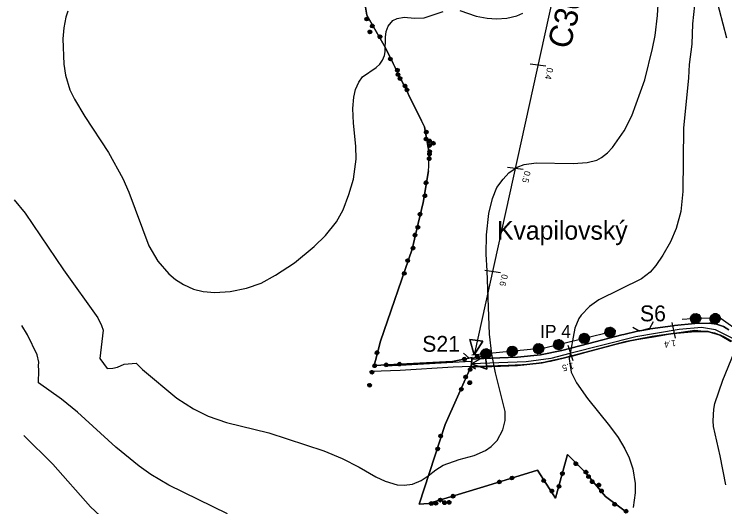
# Model space of a CAD drawing. Extents: x -645676 to -642474, y -1077513 to -1072613.
# Drawn here: x -644931 to -644259, y -1076247 to -1075781 of the extents above; entities that cross this region are included whole.
import ezdxf

# ---------------------------------------------------------------- set-up
doc = ezdxf.new("R2010")
doc.units = 0
for name, color, linetype in [('_cesty_Kunci', 7, 'Continuous'), ('Interak_n__prvek___l_niov____navr_en_', 7, 'Continuous'), ('katastr_ln___zem____popis', 7, 'Continuous'), ('KULTURY_STAV', 7, 'Continuous'), ('OBVOD_PU', 7, 'Continuous'), ('Odvodnen__cesty_pod_lnou_dren_____navr_en_', 7, 'Continuous'), ('PC_NAVRH', 7, 'Continuous'), ('PC_OBJ_POPIS_NAVRH', 7, 'Continuous'), ('PC_OBJ_POPIS_STAV', 7, 'Continuous'), ('PC_OBJEKTY_NAVRH', 7, 'Continuous'), ('PC_OBJEKTY_STAV', 7, 'Continuous'), ('PC_POPIS_NAVRH', 7, 'Continuous'), ('PC_STAN_NAVRH', 7, 'Continuous'), ('SPRAV_HR_STAV', 7, 'Continuous'), ('USES_IP_NAVRH', 7, 'Continuous'), ('VRSTEVNICE', 7, 'Continuous')]:
    doc.layers.add(name, color=color, linetype=linetype)

# ---------------------------------------------------------------- blocks, each defined once
blk = doc.blocks.new('$944')
blk.add_line((0, 1.5), (0, -1.5))
blk = doc.blocks.new('$920')
for points in [[(0, 0), (-2.8, 1.25), (-2.8, -1.25), (0, 0)], [(-2.8, 1.25), (0, 0), (-2.8, -1.25), (-2.8, 1.25)]]:
    blk.add_lwpolyline(points)
blk = doc.blocks.new('$934')
blk.add_lwpolyline([(-2, -1), (-1, 0), (1, 0), (2, -1)])
blk = doc.blocks.new('$935')
blk.add_lwpolyline([(-2, -1), (-1, 0), (1, 0), (2, -1)])
blk = doc.blocks.new('6$4100')
blk.add_lwpolyline([(0.19, 0.72), (0.53, 0.53), (0.72, 0.19), (0.72, -0.2), (0.53, -0.54), (0.19, -0.73), (-0.2, -0.73), (-0.54, -0.54), (-0.73, -0.2), (-0.75, 0.12), (-0.54, 0.52), (-0.2, 0.71), (0.19, 0.71), (0.2, 0.67), (-0.2, 0.67), (-0.36, 0.59), (0.36, 0.59), (0.44, 0.51), (-0.44, 0.51), (-0.52, 0.43), (0.52, 0.43), (0.6, 0.35), (-0.6, 0.35), (-0.6, 0.27), (0.6, 0.27), (0.68, 0.19), (-0.59, 0.19), (-0.68, 0.19), (-0.68, 0.11), (0.59, 0.11), (0.68, 0.11), (0.68, 0.03), (-0.59, 0.03), (-0.68, 0.03), (-0.68, -0.05), (0.59, -0.05), (0.68, -0.05), (0.68, -0.13), (-0.59, -0.13), (-0.68, -0.13), (-0.68, -0.21), (0.59, -0.21), (0.68, -0.21), (0.6, -0.29), (-0.6, -0.29), (-0.6, -0.37), (0.6, -0.37), (0.52, -0.45), (-0.52, -0.45), (-0.44, -0.53), (0.44, -0.53), (0.36, -0.61), (-0.36, -0.61), (-0.2, -0.69), (0.2, -0.69)])
blk = doc.blocks.new('2$0620')
for points in [[(-1.07, 0.32), (-0.88, 0.13), (-0.88, -0.14), (-1.07, -0.33), (-1.34, -0.33), (-1.53, -0.14), (-1.53, 0.13), (-1.34, 0.32), (-1.07, 0.32), (-1.08, 0.28), (-1.32, 0.28), (-1.4, 0.2), (-1, 0.2), (-0.92, 0.12), (-1.48, 0.12), (-1.48, 0.04), (-0.92, 0.04), (-0.92, -0.04), (-1.48, -0.04), (-1.48, -0.12), (-0.92, -0.12), (-1, -0.2), (-1.4, -0.2), (-1.32, -0.28), (-1.08, -0.28)], [(1.43, 0.32), (1.62, 0.13), (1.62, -0.14), (1.43, -0.33), (1.16, -0.33), (0.97, -0.14), (0.97, 0.13), (1.16, 0.32), (1.43, 0.32), (1.4, 0.28), (1.16, 0.28), (1.08, 0.2), (1.48, 0.2), (1.56, 0.12), (1, 0.12), (1, 0.04), (1.56, 0.04), (1.56, -0.04), (1, -0.04), (1, -0.12), (1.56, -0.12), (1.48, -0.2), (1.08, -0.2), (1.16, -0.28), (1.4, -0.28)]]:
    blk.add_lwpolyline(points)

msp = doc.modelspace()

# ---------------------------------------------------------------- linework, layer by layer
at = {"layer": '_cesty_Kunci'}
for points in [[(-644581.13, -1076113.83), (-644566.09, -1076113.29), (-644515.99, -1076110.21), (-644498.33, -1076109.46)], [(-644593.08, -1076118.86), (-644565.87, -1076117.78), (-644515.75, -1076114.7), (-644498.85, -1076113.98)]]:
    msp.add_lwpolyline(points, dxfattribs=at)
at = {"layer": 'KULTURY_STAV'}
for points in [[(-644255.1, -1076079.71), (-644260.19, -1076076.56), (-644266.6, -1076074.35), (-644271.34, -1076073.61), (-644272.85, -1076073.38), (-644273.34, -1076073.4), (-644287.12, -1076073.87), (-644306.47, -1076075.81), (-644308.04, -1076075.97), (-644329.62, -1076078.88), (-644330.08, -1076078.97), (-644339.27, -1076080.54), (-644339.74, -1076080.65), (-644341.46, -1076081.05), (-644354.26, -1076084.02), (-644356.27, -1076084.54), (-644387.65, -1076092.6), (-644413.15, -1076099.38), (-644433.25, -1076103.25), (-644454.88, -1076105.48), (-644463.83, -1076105.91), (-644479.69, -1076106.66), (-644493.74, -1076107.19), (-644498.09, -1076107.36), (-644497.92, -1076105.85), (-644516.5, -1076109.6), (-644590.53, -1076113.44), (-644589.33, -1076108.84), (-644584.52, -1076090.43), (-644554.64, -1076003.63), (-644548.81, -1075979.12), (-644544.12, -1075959.37), (-644539.08, -1075929.42), (-644538.91, -1075925.07), (-644538.45, -1075912.82), (-644542.92, -1075887.94), (-644545.74, -1075882.23), (-644570.68, -1075831.68), (-644572.46, -1075828.07), (-644579.81, -1075813.18), (-644597.61, -1075782.29), (-644598.84, -1075774.6)], [(-644253.28, -1076090.66), (-644263.37, -1076084.84), (-644271.64, -1076082.31), (-644274.66, -1076081.39), (-644286.82, -1076081.21), (-644307.62, -1076083.15), (-644327.55, -1076086.11), (-644353.37, -1076091.11), (-644385.16, -1076099.62), (-644411.62, -1076106.58), (-644423.38, -1076109.21), (-644431.6, -1076111.04), (-644446.18, -1076112.61), (-644454.96, -1076113.55), (-644479.38, -1076114.39), (-644494.42, -1076114.72), (-644495.74, -1076114.74), (-644499.22, -1076114.82), (-644498.85, -1076113.98), (-644497.92, -1076105.85), (-644498.09, -1076107.36), (-644493.74, -1076107.19), (-644479.69, -1076106.66), (-644463.83, -1076105.91), (-644454.88, -1076105.48), (-644433.25, -1076103.25), (-644413.15, -1076099.38), (-644387.65, -1076092.6), (-644356.27, -1076084.54), (-644354.26, -1076084.02), (-644341.46, -1076081.05), (-644339.74, -1076080.65), (-644339.27, -1076080.54), (-644330.08, -1076078.97), (-644329.62, -1076078.88), (-644308.04, -1076075.97), (-644306.47, -1076075.81), (-644287.12, -1076073.87), (-644273.34, -1076073.4), (-644272.85, -1076073.38), (-644271.34, -1076073.61), (-644266.6, -1076074.35), (-644260.19, -1076076.56), (-644255.1, -1076079.71)], [(-644351.78, -1076252.26), (-644371.8, -1076237.42), (-644391.26, -1076214.09), (-644395.44, -1076209.88), (-644407.52, -1076197.72), (-644418.96, -1076238.75), (-644435.94, -1076212.32), (-644483.15, -1076226.85), (-644539, -1076244.05), (-644543.56, -1076244.32), (-644548.02, -1076244.59), (-644523.47, -1076169.36), (-644498.85, -1076113.98), (-644499.22, -1076114.82), (-644495.74, -1076114.74), (-644494.42, -1076114.72), (-644479.38, -1076114.39), (-644454.96, -1076113.55), (-644446.18, -1076112.61), (-644431.6, -1076111.04), (-644423.38, -1076109.21), (-644411.62, -1076106.58), (-644385.16, -1076099.62), (-644353.37, -1076091.11), (-644327.55, -1076086.11), (-644307.62, -1076083.15), (-644286.82, -1076081.21)], [(-644286.82, -1076081.21), (-644274.66, -1076081.39), (-644271.64, -1076082.31), (-644263.37, -1076084.84), (-644253.28, -1076090.66)]]:
    msp.add_lwpolyline(points, dxfattribs=at)
at = {"layer": 'OBVOD_PU'}
msp.add_lwpolyline([(-644351.78, -1076252.26), (-644371.8, -1076237.42), (-644391.26, -1076214.09), (-644395.44, -1076209.88), (-644407.52, -1076197.72), (-644418.96, -1076238.75), (-644435.94, -1076212.32), (-644483.15, -1076226.85), (-644539, -1076244.05), (-644543.56, -1076244.32), (-644548.02, -1076244.59), (-644523.47, -1076169.36), (-644498.85, -1076113.98), (-644497.92, -1076105.85), (-644516.5, -1076109.6), (-644590.53, -1076113.44), (-644589.33, -1076108.84), (-644584.52, -1076090.43), (-644554.64, -1076003.63), (-644548.81, -1075979.12), (-644544.12, -1075959.37), (-644539.08, -1075929.42), (-644538.91, -1075925.07), (-644538.45, -1075912.82), (-644542.92, -1075887.94), (-644545.74, -1075882.23), (-644570.68, -1075831.68), (-644572.46, -1075828.07), (-644579.81, -1075813.18), (-644597.61, -1075782.29), (-644598.84, -1075774.6)], dxfattribs=at)
at = {"layer": 'Odvodnen__cesty_pod_lnou_dren_____navr_en_'}
msp.add_line((-644498.93, -1076114.49), (-644494.84, -1076116.47), dxfattribs=at)
msp.add_lwpolyline([(-644251.27, -1076091.08), (-644260.08, -1076086.2), (-644268.33, -1076082.83), (-644275.82, -1076081.52), (-644287.1, -1076080.49), (-644306.69, -1076083.31), (-644326.43, -1076086.54), (-644346.09, -1076089.91), (-644365.48, -1076094.52), (-644384.53, -1076099.74), (-644403.99, -1076104.97), (-644423.65, -1076109.71), (-644443.52, -1076112.41), (-644463.87, -1076113.41), (-644483.79, -1076114.02), (-644498.74, -1076114.51)], dxfattribs=at)
at = {"layer": 'PC_NAVRH'}
for points in [[(-644342.95, -1075440.67), (-644365.1, -1075509.19), (-644418.08, -1075749.44), (-644495.8, -1076103.48)], [(-644250.14, -1076088.62), (-644267.83, -1076079.85), (-644280.9, -1076077.7), (-644301.9, -1076079.35), (-644343.08, -1076086.3), (-644405.42, -1076102.02), (-644423.45, -1076106.99), (-644446.76, -1076110.13), (-644498.6, -1076111.79)]]:
    msp.add_lwpolyline(points, dxfattribs=at)
at = {"layer": 'SPRAV_HR_STAV'}
for p, q in [((-644598.84, -1075774.6), (-644597.61, -1075782.29)), ((-644597.61, -1075782.29), (-644579.81, -1075813.18)), ((-644579.81, -1075813.18), (-644572.46, -1075828.07)), ((-644572.46, -1075828.07), (-644570.68, -1075831.68)), ((-644570.68, -1075831.68), (-644545.74, -1075882.23)), ((-644545.74, -1075882.23), (-644542.92, -1075887.94)), ((-644542.92, -1075887.94), (-644538.45, -1075912.82)), ((-644538.91, -1075925.07), (-644538.45, -1075912.82)), ((-644539.08, -1075929.42), (-644538.91, -1075925.07)), ((-644539.08, -1075929.42), (-644544.12, -1075959.37)), ((-644544.12, -1075959.37), (-644548.81, -1075979.12)), ((-644548.81, -1075979.12), (-644554.64, -1076003.63)), ((-644554.64, -1076003.63), (-644584.52, -1076090.43)), ((-644584.52, -1076090.43), (-644589.33, -1076108.84)), ((-644589.33, -1076108.84), (-644590.53, -1076113.44)), ((-644516.5, -1076109.6), (-644497.92, -1076105.85)), ((-644497.92, -1076105.85), (-644498.85, -1076113.98)), ((-644590.53, -1076113.44), (-644516.5, -1076109.6)), ((-644498.85, -1076113.98), (-644523.47, -1076169.36)), ((-644523.47, -1076169.36), (-644548.02, -1076244.59)), ((-644418.96, -1076238.75), (-644407.52, -1076197.72)), ((-644407.52, -1076197.72), (-644395.44, -1076209.88)), ((-644395.44, -1076209.88), (-644391.26, -1076214.09)), ((-644483.15, -1076226.85), (-644435.94, -1076212.32)), ((-644435.94, -1076212.32), (-644418.96, -1076238.75)), ((-644391.26, -1076214.09), (-644371.8, -1076237.42)), ((-644539, -1076244.05), (-644483.15, -1076226.85)), ((-644371.8, -1076237.42), (-644351.78, -1076252.26)), ((-644548.02, -1076244.59), (-644543.56, -1076244.32)), ((-644543.56, -1076244.32), (-644539, -1076244.05))]:
    msp.add_line(p, q, dxfattribs=at)
at = {"layer": 'USES_IP_NAVRH'}
for points in [[(-644191.24, -1076127.18), (-644243.65, -1076082.59), (-644262.38, -1076069.4), (-644280.99, -1076068.78), (-644299.22, -1076070.01)], [(-644361.95, -1076080.78), (-644429.46, -1076097.04), (-644498.29, -1076103.76)]]:
    msp.add_lwpolyline(points, dxfattribs=at)
at = {"layer": 'VRSTEVNICE'}
for points in [[(-644257.02, -1075803.98), (-644270.78, -1075750.68)], [(-644448.77, -1075923.45), (-644437.18, -1075921.86), (-644402.42, -1075922.58), (-644389.1, -1075921.57), (-644379.83, -1075919.25), (-644375.49, -1075916.94), (-644369.69, -1075912.59), (-644365.06, -1075907.52), (-644354.05, -1075891.74), (-644346.67, -1075877.54), (-644334.5, -1075843.37), (-644327.12, -1075813.82), (-644324.8, -1075801.66), (-644322.48, -1075782.54), (-644321.61, -1075766.9)], [(-644287.58, -1075772.98), (-644289.32, -1075790.65), (-644290.04, -1075809.77), (-644292.65, -1075828.89), (-644293.23, -1075841.63), (-644297.86, -1075889.13), (-644298.73, -1075949.09), (-644300.47, -1075967.91), (-644304.81, -1075983.84), (-644310.32, -1075996.59), (-644317.56, -1076009.33), (-644324.22, -1076018.89), (-644329.58, -1076025.12), (-644337.54, -1076031.64), (-644378.09, -1076051.48), (-644386.78, -1076057.7), (-644394.89, -1076065.96), (-644396.96, -1076069.08), (-644400.69, -1076078.27), (-644406.11, -1076107.28), (-644404.16, -1076119.82), (-644399.09, -1076129.82), (-644388.81, -1076144.74), (-644367.96, -1076170.52), (-644359.7, -1076181.67)], [(-644880.19, -1075778.49), (-644882.11, -1075784.26), (-644884.24, -1075794.42), (-644885.11, -1075804.56), (-644884.24, -1075828.6), (-644882.51, -1075839.02), (-644878.31, -1075852.93), (-644874.11, -1075861.62), (-644864.11, -1075878.13), (-644841.81, -1075912.01)], [(-644841.81, -1075912.01), (-644828.2, -1075936.63), (-644822.7, -1075949.67), (-644803.58, -1076000.35), (-644795.32, -1076014.84), (-644784.75, -1076026.86), (-644778.38, -1076032.07), (-644770.85, -1076036.85), (-644761.58, -1076041.34), (-644752.31, -1076043.51), (-644741.31, -1076044.52), (-644726.82, -1076043.51), (-644711.18, -1076040.32), (-644697.57, -1076035.54), (-644683.81, -1076028.16), (-644666, -1076016.28), (-644647.32, -1076000.93), (-644636.6, -1075990.65), (-644626.17, -1075977.76), (-644619.95, -1075966.32), (-644614.44, -1075951.69), (-644610.24, -1075937.21), (-644607.64, -1075918.39), (-644607.78, -1075906.22), (-644609.95, -1075884.5), (-644610.68, -1075870.59), (-644609.81, -1075859.88), (-644608.07, -1075852.64), (-644605.17, -1075845.69), (-644601.55, -1075840.47), (-644588.81, -1075831.93), (-644585.33, -1075828.74), (-644582.58, -1075824.69), (-644580.84, -1075820.49), (-644580.26, -1075817.01), (-644579.97, -1075803.11), (-644579.25, -1075797.89), (-644577.22, -1075792.68), (-644572.88, -1075787.47), (-644568.68, -1075785.58), (-644562.02, -1075784.14), (-644552.46, -1075785.29), (-644543.19, -1075784.86), (-644525.23, -1075778.92)], [(-644509.59, -1075778.05), (-644493.95, -1075783.12), (-644483.52, -1075785), (-644474.83, -1075785.73), (-644464.99, -1075785.29), (-644455.72, -1075782.98), (-644449.78, -1075780.37)], [(-644848.33, -1076075.66), (-644846.88, -1076080), (-644850.15, -1076106.84), (-644843.15, -1076116.45), (-644837.8, -1076115.83), (-644833.27, -1076115.01), (-644827.1, -1076112.36), (-644815.78, -1076111.13), (-644809.66, -1076117.22), (-644777.08, -1076144.31), (-644761.29, -1076154.44), (-644747.68, -1076161.4), (-644730.3, -1076167.19), (-644690.04, -1076177.18), (-644638.19, -1076194.12), (-644620.81, -1076201.51), (-644604.88, -1076209.48), (-644588.95, -1076218.74), (-644580.26, -1076222.94), (-644568.68, -1076226.42), (-644562.31, -1076226.71), (-644554.2, -1076225.55), (-644546.09, -1076222.22), (-644539.42, -1076217.88), (-644532.33, -1076211.94), (-644525.23, -1076207.59), (-644510.17, -1076202.23), (-644495.98, -1076198.47), (-644485.26, -1076193.84), (-644479.76, -1076190.07), (-644474.26, -1076184.42), (-644468.75, -1076174.14), (-644466.58, -1076165.45), (-644466.72, -1076157.05), (-644475.85, -1076120.27), (-644479.18, -1076102.89), (-644481.5, -1076083.77), (-644483.52, -1076024.1), (-644484.68, -1076008.17), (-644484.39, -1075989.93), (-644482.22, -1075969.65), (-644478.74, -1075955.46), (-644474.4, -1075945.32), (-644468.61, -1075937.21), (-644463.1, -1075931.42), (-644455.43, -1075926.06), (-644448.77, -1075923.45)], [(-644931.02, -1075956.91), (-644920.59, -1075969.51), (-644884.53, -1076022.95), (-644851.95, -1076068.42), (-644848.33, -1076075.66)], [(-644729.29, -1076253.79), (-644784.75, -1076226.71), (-644801.84, -1076216.43), (-644812.85, -1076208.75), (-644835, -1076190.65), (-644871.21, -1076157.63), (-644886.27, -1076145.32), (-644908.14, -1076129.97), (-644907.59, -1076117.91), (-644907.99, -1076113.89), (-644907.85, -1076110.42), (-644909.15, -1076103.47), (-644918.57, -1076084.35), (-644923.78, -1076075.66)], [(-644257.89, -1076226.27), (-644263.25, -1076198.76), (-644269.48, -1076171.24), (-644269.91, -1076165.74), (-644269.33, -1076154.73), (-644268.17, -1076149.23), (-644260.64, -1076127.22), (-644247.32, -1076094.2)], [(-644922.04, -1076179.5), (-644894.53, -1076206.58), (-644858.76, -1076247.13), (-644835.73, -1076268.42), (-644816.03, -1076283.04)], [(-644359.7, -1076181.67), (-644353.47, -1076192.1), (-644349.27, -1076200.79), (-644345.8, -1076211.21), (-644343.77, -1076225.12), (-644343.63, -1076233.81), (-644345.51, -1076247.71)]]:
    msp.add_lwpolyline(points, dxfattribs=at)

# ---------------------------------------------------------------- block references
at = {"layer": 'PC_OBJEKTY_NAVRH', "xscale": 5, "yscale": 5.000000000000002, "rotation": -176.83466300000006}
msp.add_blockref('$935', (-644495.77, -1076106.26), dxfattribs=at)
at = {"layer": 'PC_OBJEKTY_STAV', "xscale": 4.999999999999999, "yscale": 5, "rotation": -164.94232399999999}
msp.add_blockref('$934', (-644335.01, -1076079.72), dxfattribs=at)
at = {"layer": 'PC_STAN_NAVRH'}
for name, p, xscale, yscale, rotation in [('$944', (-644435.65, -1075829.51), 5, 5.000000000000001, -97.88467400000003), ('$944', (-644457.1, -1075927.18), 5, 5.000000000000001, -97.88467400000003), ('$944', (-644478.54, -1076024.85), 5, 5.000000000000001, -97.88467400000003), ('$944', (-644307.11, -1076080.23), 5, 5, -167.11092599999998), ('$920', (-644495.8, -1076103.48), 5, 5.000000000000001, -97.88467400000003), ('$944', (-644404.67, -1076101.83), 4.999999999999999, 5.000000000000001, -162.45891500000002), ('$920', (-644498.6, -1076111.79), 5, 5, -174.99834000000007)]:
    msp.add_blockref(name, p, dxfattribs=dict(at, xscale=xscale, yscale=yscale, rotation=rotation))
at = {"layer": 'SPRAV_HR_STAV'}
for p, xscale, yscale, rotation in [((-644596.08, -1075791.88), 5, 5.000000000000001, -76.04163000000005), ((-644588.87, -1075797.45), 5, 5, -54.812662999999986), ((-644572.06, -1075828.87), 5, 5, -58.55722200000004), ((-644564.72, -1075843.77), 5, 5, -58.58276800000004), ((-644562.94, -1075847.37), 5.000000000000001, 5, -58.56878600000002), ((-644537.99, -1075897.92), 4.999999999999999, 5.000000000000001, -58.545462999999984), ((-644539.83, -1075905.16), 5, 5.000000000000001, -74.924612), ((-644538.25, -1075907.58), 5, 5, 89.38275999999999), ((-644538.4, -1075911.93), 5, 4.999999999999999, 89.293731), ((-644541.98, -1075946.68), 4.999999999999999, 5, -95.00659400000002), ((-644548.16, -1075976.4), 5, 5.000000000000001, -98.87927200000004), ((-644552.86, -1075996.15), 5.000000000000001, 5.000000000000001, -98.90098199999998), ((-644560.34, -1076020.18), 5, 5.000000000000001, -104.61463800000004), ((-644588.94, -1076107.36), 4.999999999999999, 5.000000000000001, -100.18559200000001), ((-644499.35, -1076106.14), 5, 4.999999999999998, 11.609866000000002), ((-644573.05, -1076112.53), 5, 5, 3.021145), ((-644499.91, -1076123.24), 5, 4.999999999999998, -91.92726), ((-644593.75, -1076125.77), 5.000000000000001, 5, -100.16365899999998), ((-644505.96, -1076129.97), 5, 5, -109.67418900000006), ((-644528.9, -1076186), 5.000000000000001, 5.000000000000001, -103.67624700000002), ((-644395.19, -1076210.14), 5, 5, -39.69460800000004), ((-644414.26, -1076221.89), 4.999999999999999, 5.000000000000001, 75.719325), ((-644383.11, -1076222.3), 5, 5, -39.710648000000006), ((-644466.42, -1076221.7), 5.000000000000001, 5, 17.405565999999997), ((-644426.48, -1076227.04), 5, 4.999999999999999, -51.997768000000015), ((-644380.05, -1076227.53), 5, 5, -44.76027499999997), ((-644522.28, -1076238.9), 4.999999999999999, 5.000000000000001, 17.415896), ((-644530.55, -1076243.53), 5.000000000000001, 5, 3.5248149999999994), ((-644526.09, -1076243.29), 5, 5.000000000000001, 3.4476979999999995), ((-644357.74, -1076247.84), 4.999999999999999, 4.999999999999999, -30.90270199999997)]:
    msp.add_blockref('2$0620', p, dxfattribs=dict(at, xscale=xscale, yscale=yscale, rotation=rotation))
at = {"layer": 'USES_IP_NAVRH'}
for p, xscale, yscale, rotation in [((-644286.62, -1076069.16), 6.5, 6.5, -172.91075500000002), ((-644268.03, -1076069.21), 6.500000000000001, 6.499999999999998, -178.81246200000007), ((-644391.75, -1076087.96), 6.5, 6.5, -163.086946), ((-644367.44, -1076082.11), 6.5, 6.5, -163.086946), ((-644416.05, -1076093.81), 6.5, 6.5, -163.086946), ((-644459.96, -1076100.02), 6.5, 6.5, -171.17972900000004), ((-644435.08, -1076097.59), 6.5, 6.5, -171.17972900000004), ((-644484.85, -1076102.45), 6.5, 6.5, -171.17972900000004)]:
    msp.add_blockref('6$4100', p, dxfattribs=dict(at, xscale=xscale, yscale=yscale, rotation=rotation))

# ---------------------------------------------------------------- texts
at = {"layer": 'Interak_n__prvek___l_niov____navr_en_'}
msp.add_text('IP 4', height=12.25, dxfattribs=at).set_placement((-644433.58, -1076087.35))
at = {"layer": 'katastr_ln___zem____popis'}
msp.add_text('Kvapilovský', height=17.5, dxfattribs=at).set_placement((-644474.36, -1075994.5))
at = {"layer": 'PC_OBJ_POPIS_NAVRH'}
msp.add_text('S21', height=15, dxfattribs=at).set_placement((-644545.08, -1076100.52))
at = {"layer": 'PC_OBJ_POPIS_STAV'}
msp.add_text('S6', height=15, dxfattribs=at).set_placement((-644339.13, -1076071.7))
at = {"layer": 'PC_POPIS_NAVRH'}
msp.add_text('C30', height=22, rotation=75.573, dxfattribs=at).set_placement((-644405.6, -1075815.37))
at = {"layer": 'PC_STAN_NAVRH'}
for s, rotation, p in [('0.4', 257.602, (-644426.86, -1075831.43)), ('0.5', 257.602, (-644448.3, -1075929.1)), ('0.6', 257.602, (-644469.75, -1076026.78)), ('1.4', 189.592, (-644305.6, -1076089.11)), ('1.5', 194.175, (-644402.47, -1076110.56))]:
    msp.add_text(s, height=6, rotation=rotation, dxfattribs=at).set_placement(p)

doc.saveas('drawing.dxf')
